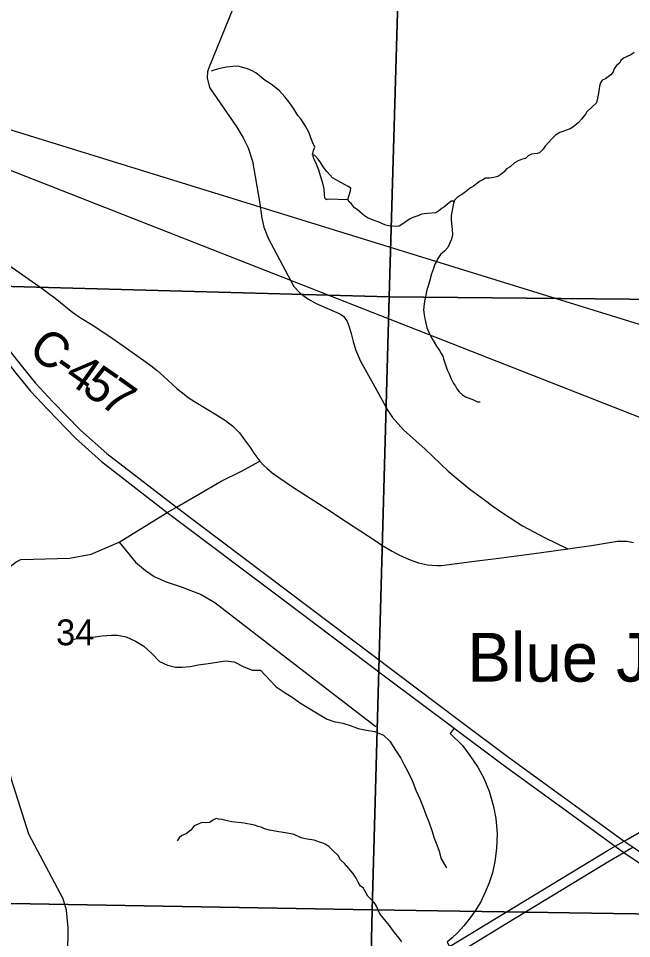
# Model space of a CAD drawing. Extents: x -7.5 to 26.5, y 3.5 to 25.5.
# Drawn here: x -1.909 to -0.916, y 19.097 to 20.587 of the extents above; entities that cross this region are included whole.
import ezdxf

# ---------------------------------------------------------------- set-up
doc = ezdxf.new("R2010")
doc.units = 0
for name, color, linetype in [('GM_X_Corporation', 7, 'Continuous'), ('GM_X_County_Road', 7, 'Continuous'), ('GM_X_County_Road_Text', 7, 'Continuous'), ('GM_X_Interchange_Ramps', 7, 'Continuous'), ('GM_X_Interstate_Route', 7, 'Continuous'), ('GM_X_Minor_River', 7, 'Continuous'), ('GM_X_Section_Text', 7, 'Continuous'), ('GM_X_Township_Road', 7, 'Continuous'), ('GM_X_Unincorporated_Text', 7, 'Continuous'), ('GM_X_US_Route', 7, 'Continuous'), ('SH_Text', 7, 'Continuous')]:
    doc.layers.add(name, color=color, linetype=linetype)

msp = doc.modelspace()

# ---------------------------------------------------------------- linework, layer by layer
at = {"layer": 'GM_X_Corporation'}
for points in [[(-2.268, 21.1618), (-1.2798, 21.1309), (-1.3089, 20.136), (-2.2948, 20.1631)], [(-1.2798, 21.1309), (-1.0307, 21.1237), (-0.2705, 21.1018), (-0.3082, 20.1265), (-1.3089, 20.136)], [(-2.2948, 20.1631), (-1.3089, 20.136), (-1.3364, 19.1437), (-2.3216, 19.1609)], [(-1.3089, 20.136), (-0.3082, 20.1265), (-0.3419, 19.1283), (-1.3364, 19.1437)], [(-1.3364, 19.1437), (-1.3579, 18.1948), (-1.3746, 18.1766), (-1.4066, 18.1528), (-1.412, 18.1491), (-2.3477, 18.203), (-2.3216, 19.1609)], [(-0.3419, 19.1283), (-0.3746, 18.1372), (-1.2757, 18.1481), (-1.2769, 18.1576), (-1.2831, 18.1672), (-1.2995, 18.1782), (-1.3164, 18.1862), (-1.3281, 18.1892), (-1.3372, 18.1894), (-1.3579, 18.1948), (-1.3364, 19.1437)]]:
    msp.add_lwpolyline(points, close=True, dxfattribs=at)
at = {"layer": 'GM_X_County_Road'}
for points in [[(-1.5624, 20.6027), (-1.6012, 20.5072), (-1.6031, 20.5005), (-1.6035, 20.4909), (-1.6001, 20.4755), (-1.5558, 20.4108), (-1.5452, 20.3935), (-1.5375, 20.3777), (-1.5305, 20.3562), (-1.5188, 20.2904), (-1.515, 20.2637), (-1.5118, 20.2489), (-1.5048, 20.2311), (-1.4633, 20.1528), (-1.4532, 20.1422), (-1.4406, 20.133), (-1.4272, 20.1255), (-1.389, 20.109), (-1.3829, 20.1047), (-1.377, 20.0961), (-1.3735, 20.0875), (-1.3704, 20.077), (-1.3672, 20.0638), (-1.3637, 20.051), (-1.3553, 20.032), (-1.3321, 19.9903), (-1.3113, 19.952), (-1.3038, 19.9407), (-1.286, 19.9207), (-1.2505, 19.8895), (-1.2135, 19.8541), (-1.1786, 19.8246), (-1.1548, 19.8075), (-1.1409, 19.7972), (-1.122, 19.7844), (-1.0929, 19.7653), (-1.0573, 19.7467), (-1.0197, 19.7282)], [(-1.9613, 20.213), (-1.8927, 20.165), (-1.8707, 20.1495), (-1.8599, 20.1418), (-1.85, 20.134), (-1.8237, 20.1128), (-1.8158, 20.1071), (-1.8075, 20.1018), (-1.79, 20.0911), (-1.7646, 20.0742), (-1.7381, 20.0557), (-1.7101, 20.0359), (-1.6946, 20.0246), (-1.6847, 20.0168), (-1.6739, 20.0071), (-1.6526, 19.9879), (-1.6412, 19.9785), (-1.6343, 19.9732), (-1.6243, 19.9666), (-1.5884, 19.9449), (-1.5739, 19.9358), (-1.5619, 19.9266), (-1.5516, 19.9161), (-1.543, 19.9048), (-1.5337, 19.8915), (-1.5283, 19.8833), (-1.5182, 19.8701), (-1.5123, 19.8635), (-1.5071, 19.8586), (-1.4987, 19.8512), (-1.4878, 19.8435), (-1.4638, 19.8277), (-1.4101, 19.7931), (-1.3783, 19.7721), (-1.3318, 19.7415), (-1.3207, 19.7343), (-1.3043, 19.7244), (-1.2935, 19.7187), (-1.2815, 19.7129), (-1.2724, 19.7093), (-1.2614, 19.7056), (-1.2467, 19.7023), (-1.2399, 19.7016), (-1.2314, 19.7013), (-1.2242, 19.7014), (-1.2162, 19.702), (-1.1709, 19.7081), (-1.127, 19.7134), (-1.0621, 19.7223), (-1.0197, 19.7282), (-0.9816, 19.7337), (-0.9488, 19.739), (-0.9391, 19.7404), (-0.9307, 19.7407), (-0.9239, 19.7405), (-0.9133, 19.7386)], [(-1.8306, 18.985), (-1.8288, 19.1143), (-1.8314, 19.143), (-1.8371, 19.1612), (-1.8924, 19.2661), (-1.9204, 19.3547), (-1.9464, 19.471), (-1.9496, 19.5216), (-1.9429, 19.6724), (-1.9404, 19.6814), (-1.9347, 19.6903), (-1.9129, 19.707), (-1.9056, 19.711), (-1.8851, 19.7114), (-1.8266, 19.7132), (-1.7915, 19.7193), (-1.7464, 19.739), (-1.6687, 19.7871), (-1.6536, 19.7958), (-1.6162, 19.8174), (-1.5808, 19.8379), (-1.5491, 19.8536), (-1.5182, 19.8701)]]:
    msp.add_lwpolyline(points, dxfattribs=at)
at = {"layer": 'GM_X_Interchange_Ramps'}
for points in [[(-1.2037, 19.4375), (-1.2102, 19.429), (-1.1903, 19.4096), (-1.1781, 19.3933), (-1.1655, 19.3745), (-1.1558, 19.3565), (-1.1472, 19.3359), (-1.1398, 19.311), (-1.1362, 19.2913), (-1.1343, 19.2674), (-1.135, 19.243), (-1.1379, 19.2216), (-1.1419, 19.2037), (-1.1471, 19.1873), (-1.1533, 19.172), (-1.1608, 19.1567), (-1.1695, 19.1421), (-1.1776, 19.1305), (-1.188, 19.1175), (-1.1985, 19.1063), (-1.2068, 19.0983), (-1.2153, 19.0911), (-1.2112, 19.0844)], [(-1.3415, 18.9855), (-1.1183, 19.1219), (-0.9523, 19.2229), (-0.9291, 19.2366), (-0.9201, 19.2419), (-0.9141, 19.2451)]]:
    msp.add_lwpolyline(points, dxfattribs=at)
at = {"layer": 'GM_X_Interstate_Route'}
msp.add_line((-1.3147, 19.5211), (-1.2037, 19.4375), dxfattribs=at)
for points in [[(-2.57, 20.6377), (-2.525, 20.6087), (-2.2647, 20.439), (-2.2513, 20.4293), (-2.2377, 20.4188), (-2.2096, 20.3973), (-2.1816, 20.3705), (-2.1587, 20.3469), (-2.1355, 20.3188), (-2.1158, 20.292), (-2.0919, 20.2573), (-1.9368, 20.0429), (-1.9135, 20.0126), (-1.8898, 19.9837), (-1.8618, 19.9538), (-1.817, 19.9075), (-1.7747, 19.8698), (-1.6687, 19.7871), (-1.4843, 19.649), (-1.3147, 19.5211)], [(-2.5166, 20.6214), (-2.2641, 20.4567), (-2.2429, 20.4419), (-2.2259, 20.4305), (-2.2012, 20.4099), (-2.1752, 20.3875), (-2.1502, 20.3617), (-2.125, 20.3321), (-2.1026, 20.3014), (-2.0717, 20.2574), (-1.9284, 20.0555), (-1.9051, 20.0252), (-1.8815, 19.9963), (-1.8534, 19.9664), (-1.8086, 19.9202), (-1.7663, 19.8824), (-1.6536, 19.7958), (-1.4759, 19.6616), (-1.1953, 19.4501), (-1.116, 19.3907), (-0.9284, 19.2549), (-0.9141, 19.2451), (-0.7414, 19.1282), (-0.5126, 18.9753)], [(-1.2037, 19.4375), (-1.1244, 19.3781), (-0.9429, 19.2465), (-0.9291, 19.2366), (-0.7498, 19.1155), (-0.546, 18.9794)], [(-1.2112, 19.0844), (-0.9544, 19.2399), (-0.9429, 19.2465), (-0.9284, 19.2549), (-0.8938, 19.2749), (-0.8665, 19.2868), (-0.8345, 19.2963), (-0.8066, 19.3004), (-0.7722, 19.3004), (-0.7389, 19.2945), (-0.7033, 19.2844), (-0.676, 19.2702), (-0.6511, 19.2529), (-0.6285, 19.2327), (-0.606, 19.2042), (-0.5887, 19.1775), (-0.5709, 19.1401), (-0.5442, 19.0724)]]:
    msp.add_lwpolyline(points, dxfattribs=at)
at = {"layer": 'GM_X_Minor_River'}
for points in [[(-0.9294, 20.523), (-0.9337, 20.519), (-0.9361, 20.5145), (-0.9408, 20.5109), (-0.9448, 20.5053), (-0.9465, 20.5004), (-0.95, 20.496), (-0.9586, 20.4894), (-0.964, 20.4873), (-0.9668, 20.4829), (-0.9685, 20.4772), (-0.969, 20.4731), (-0.97, 20.4663), (-0.9718, 20.458), (-0.9728, 20.4534), (-0.9733, 20.4506)], [(-0.9123, 20.5319), (-0.9178, 20.5283), (-0.9294, 20.523)], [(-1.4333, 20.3661), (-1.4317, 20.3732), (-1.4291, 20.3784), (-1.4326, 20.3854), (-1.4357, 20.3935), (-1.4385, 20.4016), (-1.4442, 20.4128), (-1.4471, 20.4171), (-1.4521, 20.4244), (-1.4569, 20.4299), (-1.4633, 20.4408), (-1.471, 20.4513), (-1.4779, 20.4603), (-1.4863, 20.4697), (-1.4981, 20.4792), (-1.5044, 20.4836), (-1.51, 20.4865), (-1.5155, 20.4913), (-1.5196, 20.4948), (-1.5247, 20.4992), (-1.5307, 20.5024), (-1.5382, 20.5057), (-1.5457, 20.5079), (-1.554, 20.5097), (-1.5623, 20.5092), (-1.5723, 20.508), (-1.5807, 20.5068), (-1.5872, 20.5051), (-1.5925, 20.5034), (-1.5972, 20.5017)], [(-0.9733, 20.4506), (-0.9889, 20.4361), (-0.991, 20.432), (-0.9973, 20.4239), (-1.0025, 20.4184), (-1.0068, 20.4147), (-1.0114, 20.4111), (-1.0157, 20.4086), (-1.0207, 20.4065), (-1.0261, 20.4047), (-1.0326, 20.4023), (-1.0396, 20.398), (-1.0459, 20.3917), (-1.0506, 20.387), (-1.0566, 20.38), (-1.0597, 20.3755), (-1.0653, 20.3696), (-1.0695, 20.3682), (-1.0741, 20.368), (-1.0786, 20.3674), (-1.0837, 20.3646), (-1.0884, 20.3602), (-1.0945, 20.3585), (-1.1003, 20.3564), (-1.1061, 20.3532), (-1.1131, 20.347), (-1.1189, 20.3437), (-1.1229, 20.3385), (-1.128, 20.3345), (-1.133, 20.3313), (-1.1395, 20.3296), (-1.1472, 20.3287), (-1.1529, 20.3282), (-1.1571, 20.3257), (-1.1626, 20.3228), (-1.1676, 20.3192), (-1.1731, 20.3152), (-1.1773, 20.3127), (-1.1828, 20.3083), (-1.1879, 20.3043), (-1.1941, 20.3004), (-1.1991, 20.2971), (-1.2031, 20.2927), (-1.2048, 20.2882), (-1.2057, 20.2818), (-1.2075, 20.2735), (-1.2085, 20.2682), (-1.2087, 20.2621), (-1.2082, 20.2552), (-1.207, 20.2453), (-1.2065, 20.2369), (-1.2079, 20.2298), (-1.2141, 20.2163), (-1.2196, 20.21), (-1.2259, 20.2049), (-1.2303, 20.1986), (-1.2323, 20.1937), (-1.2351, 20.1889), (-1.2373, 20.1821), (-1.2389, 20.178), (-1.2402, 20.1735), (-1.2432, 20.1633), (-1.2463, 20.152), (-1.248, 20.1475), (-1.2503, 20.1362), (-1.252, 20.1291), (-1.2531, 20.12), (-1.2533, 20.115), (-1.2524, 20.107), (-1.2511, 20.1005), (-1.2501, 20.0963), (-1.2478, 20.086), (-1.2461, 20.081), (-1.2422, 20.0732), (-1.2375, 20.0655), (-1.2325, 20.0565), (-1.2274, 20.0495), (-1.225, 20.0445), (-1.2221, 20.0402), (-1.2211, 20.0356), (-1.218, 20.0264), (-1.2149, 20.0183), (-1.2117, 20.0114), (-1.2085, 20.0037), (-1.2046, 19.9959), (-1.2017, 19.9916), (-1.1992, 19.9874), (-1.1956, 19.9823), (-1.1904, 19.9776), (-1.1856, 19.9744), (-1.177, 19.971), (-1.1725, 19.9693), (-1.1658, 19.9664), (-1.1616, 19.9663)], [(-1.3761, 20.2938), (-1.3714, 20.3079), (-1.3709, 20.3124), (-1.3754, 20.3148), (-1.3873, 20.3216), (-1.4008, 20.3292), (-1.4101, 20.3393), (-1.4159, 20.347), (-1.4207, 20.3548), (-1.4247, 20.3598), (-1.4295, 20.3649), (-1.4333, 20.3661), (-1.4323, 20.3619), (-1.4279, 20.3527), (-1.4233, 20.3419), (-1.4205, 20.3327), (-1.4177, 20.3224), (-1.415, 20.3109), (-1.4145, 20.3018), (-1.4139, 20.2964), (-1.4109, 20.2941), (-1.4078, 20.2951)], [(-1.4078, 20.2951), (-1.3761, 20.2938)], [(-1.2036, 20.2913), (-1.2085, 20.291), (-1.2143, 20.2862), (-1.219, 20.2826), (-1.2237, 20.2793), (-1.2284, 20.2753), (-1.2334, 20.2724), (-1.2467, 20.271), (-1.2524, 20.2708), (-1.2566, 20.2702), (-1.2609, 20.2681), (-1.2705, 20.2646), (-1.2763, 20.2622), (-1.2813, 20.2585), (-1.2883, 20.2534), (-1.2926, 20.2509), (-1.2972, 20.2503), (-1.3036, 20.2506), (-1.3097, 20.2512), (-1.3146, 20.2525), (-1.3198, 20.2545), (-1.3243, 20.2566), (-1.3333, 20.2599), (-1.343, 20.2637), (-1.349, 20.2677), (-1.3564, 20.2737), (-1.3608, 20.2776), (-1.3652, 20.2804), (-1.3699, 20.2871), (-1.374, 20.2899), (-1.3761, 20.2938)], [(-1.8234, 19.581), (-1.8104, 19.5841), (-1.7971, 19.5849), (-1.785, 19.5854), (-1.7736, 19.587), (-1.7588, 19.5881), (-1.7489, 19.5882), (-1.735, 19.5856), (-1.72, 19.5788), (-1.7062, 19.5704), (-1.6929, 19.558), (-1.6811, 19.5459), (-1.668, 19.5395), (-1.6548, 19.5365), (-1.6442, 19.5366), (-1.6313, 19.5378), (-1.6183, 19.5401), (-1.6058, 19.5417), (-1.5947, 19.5437), (-1.5848, 19.5453), (-1.5742, 19.5466), (-1.5598, 19.5451), (-1.5441, 19.5371), (-1.5302, 19.5318), (-1.5174, 19.5318)], [(-1.5174, 19.5318), (-1.5016, 19.5148), (-1.492, 19.5047), (-1.4775, 19.4951), (-1.4644, 19.4868), (-1.454, 19.4792), (-1.4443, 19.4736), (-1.4346, 19.4673), (-1.4215, 19.4593), (-1.4096, 19.4525), (-1.3987, 19.4484), (-1.3839, 19.4457), (-1.3704, 19.4415), (-1.3591, 19.437), (-1.3459, 19.4343), (-1.3323, 19.4324), (-1.3184, 19.4263), (-1.3081, 19.4165), (-1.2986, 19.4022), (-1.2899, 19.389), (-1.2845, 19.3782), (-1.2794, 19.3686), (-1.2719, 19.3531), (-1.2659, 19.3374), (-1.2591, 19.3235), (-1.2538, 19.3097), (-1.2496, 19.2978), (-1.245, 19.2858), (-1.2401, 19.272), (-1.2359, 19.2594), (-1.232, 19.249), (-1.2281, 19.2386), (-1.2247, 19.2263), (-1.2164, 19.2113)], [(-1.2887, 19.0916), (-1.293, 19.0975), (-1.2981, 19.1041), (-1.3035, 19.1112), (-1.3086, 19.1182), (-1.3137, 19.1244), (-1.3185, 19.1303), (-1.3239, 19.1373), (-1.326, 19.142), (-1.3296, 19.1493), (-1.3328, 19.1547), (-1.3434, 19.1658), (-1.3513, 19.1793), (-1.3554, 19.1821), (-1.359, 19.1883), (-1.3622, 19.1949), (-1.368, 19.2027), (-1.3741, 19.2105), (-1.3815, 19.2188), (-1.3877, 19.2243), (-1.3913, 19.2313), (-1.399, 19.2384), (-1.4063, 19.2458), (-1.4115, 19.2491), (-1.416, 19.2515), (-1.422, 19.2532), (-1.4303, 19.2562), (-1.442, 19.2581), (-1.4473, 19.259), (-1.4514, 19.2603), (-1.4626, 19.2657), (-1.4766, 19.268), (-1.4879, 19.27), (-1.503, 19.2724), (-1.5109, 19.2749), (-1.5165, 19.2774), (-1.521, 19.2787), (-1.527, 19.2808), (-1.5436, 19.284), (-1.564, 19.2863), (-1.5734, 19.2881), (-1.5802, 19.2899), (-1.5851, 19.2904), (-1.5893, 19.2913), (-1.5939, 19.2888), (-1.6001, 19.2849), (-1.6043, 19.2846), (-1.6089, 19.2848), (-1.6134, 19.2842), (-1.6184, 19.2825), (-1.6246, 19.2793), (-1.6302, 19.2726), (-1.6376, 19.2668), (-1.6449, 19.264), (-1.6492, 19.26), (-1.6524, 19.2555)]]:
    msp.add_lwpolyline(points, dxfattribs=at)
at = {"layer": 'GM_X_Township_Road'}
msp.add_lwpolyline([(-1.7464, 19.739), (-1.7199, 19.7066), (-1.7037, 19.6931), (-1.6896, 19.6832), (-1.6702, 19.6746), (-1.6443, 19.6661), (-1.6136, 19.6541), (-1.5913, 19.6415), (-1.4823, 19.5568), (-1.3306, 19.4403)], dxfattribs=at)
at = {"layer": 'GM_X_US_Route'}
msp.add_line((-1.3147, 19.5211), (-1.2037, 19.4375), dxfattribs=at)
for points in [[(-2.57, 20.6377), (-2.525, 20.6087), (-2.2647, 20.439), (-2.2513, 20.4293), (-2.2377, 20.4188), (-2.2096, 20.3973), (-2.1816, 20.3705), (-2.1587, 20.3469), (-2.1355, 20.3188), (-2.1158, 20.292), (-2.0919, 20.2573), (-1.9368, 20.0429), (-1.9135, 20.0126), (-1.8898, 19.9837), (-1.8618, 19.9538), (-1.817, 19.9075), (-1.7747, 19.8698), (-1.6687, 19.7871), (-1.4843, 19.649), (-1.3147, 19.5211)], [(-1.2037, 19.4375), (-1.1244, 19.3781), (-0.9429, 19.2465), (-0.9291, 19.2366), (-0.7498, 19.1155), (-0.546, 18.9794)]]:
    msp.add_lwpolyline(points, dxfattribs=at)
at = {"layer": 'SH_Text'}
msp.add_lwpolyline([(2.5135, 19.0346), (-2.7067, 20.6498), (2.5135, 18.5999)], close=True, dxfattribs=at)

# ---------------------------------------------------------------- texts
at = {"layer": 'GM_X_County_Road_Text'}
for s, rotation, p in [('C', 323.0773, (-1.896, 20.0453)), ('-', 325.1549, (-1.8568, 20.0159)), ('4', 325.2088, (-1.8376, 20.0026)), ('5', 325.1588, (-1.8089, 19.9826)), ('7', 324.6116, (-1.7803, 19.9627))]:
    msp.add_text(s, height=0.0568, rotation=rotation, dxfattribs=at).set_placement(p)
at = {"layer": 'GM_X_Section_Text'}
msp.add_text('34', height=0.04186, rotation=0, dxfattribs=at).set_placement((-1.8484, 19.572))
at = {"layer": 'GM_X_Unincorporated_Text'}
msp.add_text('Blue Jay', height=0.07898, rotation=0, dxfattribs=at).set_placement((-1.1822, 19.5131))

doc.saveas('drawing.dxf')
